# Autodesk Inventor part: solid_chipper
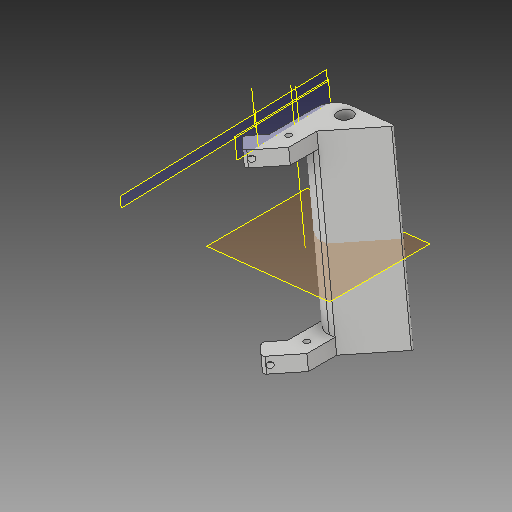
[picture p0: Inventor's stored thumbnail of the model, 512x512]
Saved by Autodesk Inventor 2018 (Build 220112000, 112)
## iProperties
Created: 2019-04
Part Number: solid_chipper
Material: Generic
Document SubType Name: Modeling
Designer: steve
Density: 1 g/cm^3
Appearance: Default
Created: 2019-05
Part Number: solid_chipper_3DPrint
Author: steve
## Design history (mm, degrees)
derived "side_assembly.iam"
sketch "Sketch1"
  geometry: L1 (-8.408, -4.5)-(67.651, -4.5); L2 (0, 0)-(22, 0) reference; L3 (11, 22.467)-(11, -9.554); L4 (17.451, -4.5)-(60.251, 38.3); L5 (17.451, 16.9)-(75.835, 16.9); L6 (26.011, -7.645)-(26.011, 49.186); L7 (36.557, -11.07)-(-5.296, 30.783); L8 (15, -3)-(7, -3); L9 (7, -3)-(7, 20); L10 (7, 20)-(15, 20); L11 (15, 20)-(15, -3); L12 (15, -3)-(7, 20); L13 (7, -3)-(15, 20); L14 (-15.558, -3)-(66.371, -3); L15 (28.487, -3)-(15, 10.487); L16 (15, 10.487)-(15, 20); L17 (-0.485, 35.485)-(40.435, -5.435); L18 (7.222, 27.778)-(2.465, 23.022); L19 (15, 20)-(7.222, 27.778); L20 (7.222, 27.778)-(2.465, 23.022); L21 (2.465, 23.022)-(7, 18.487); L22 (7, 18.487)-(7, -3); L23 (7, -3)-(28.487, -3); C1 r 7.5 at (16.699, 35.461); C2 r 4 at (16.699, 35.461) reference; C3 r 2.5 at (11, 16) reference; C4 r 1 at (11, 16); A1 r 21.4 centre (38.851, 16.9) between (17.451, 16.9) and (23.719, 1.768); 3 further points
  constraints: 44 end point, 16 point on line, 4 horizontal, 4 midpoint, 4 parallel, 3 centre point, 3 collinear, 3 perpendicular, 3 tangent, 3 vertical, 2 point on circle, 1 coincident, 1 concentric
  dimensions: "d17" = 4.5 distance between parallel lines of L1 L2; "d19" = 42.8 diameter of A1; "d21" = 15 diameter of C1; "d22" = 45 deg angle of L4 L1; "d23" = 8.56 distance from line of L6 L5.start; "d24" = 8 distance between parallel lines of L11 L9; "d25" = 3 distance between parallel lines of L2 L14; "d26" = 4 distance from line of C3.centre L10; "d32" = 11 distance from line of L18 C3.centre; "d39" = 2 diameter of C4
extrude "Extrusion1" new body sketch "Sketch1" distance "d40" = 5; taper "d41" = 0 deg
sketch "Sketch2"
  geometry: L1 (28.487, -3)-(15, 10.487) reference; L2 (7, -3)-(28.487, -3) reference; L3 (15, 10.487)-(7, 10.487); L4 (7, 10.487)-(7, -3); 1 further point
  constraints: 4 end point, 1 horizontal, 1 perpendicular
extrude "Extrusion2" join sketch "Sketch2" distance "d42" = 26.25; taper "d43" = 0 deg
mirror "Mirror1"
fillet "Fillet1" dims "d44" = 6
fillet "Fillet2" dims "d45" = 0.5
sketch "Sketch3"
  geometry: L1 (0, 0)-(0, -5) reference; L2 (0, -2.5)-(13.202, -2.5); L3 (2, -5)-(2, 20.813); 2 further points
  constraints: 4 end point, 2 point on line, 1 horizontal, 1 midpoint, 1 vertical
  dimensions: "d46" = 2 distance between parallel lines of L1 L3
hole "Hole1" sketch "Sketch3" at (2, -2.5) diameter "d47" = 2; stored, may be unused: countersink angle "d51" = 90 deg, drill point angle "d53" = 118 deg; dims "d48" = 6, "d49" = 4, "d50" = 2, "d52" = 8
sketch "Sketch4"
  geometry: L1 (6.727, 0)-(6.727, -5) reference; L2 (6.727, -2.5)-(0, -2.5); L3 (0, 0)-(0, -5) reference; L4 (0, -5)-(6.727, -5) reference; L5 (3.727, -5)-(3.727, 0); 2 further points
  constraints: 4 end point, 3 midpoint, 1 point on line, 1 vertical
  dimensions: "d54" = 3 distance between parallel lines of L1 L5
hole "Hole2" sketch "Sketch4" at (3.727, -2.5) diameter "d55" = 2; stored, may be unused: countersink angle "d59" = 90 deg, drill point angle "d61" = 118 deg; dims "d56" = 6, "d57" = 4, "d58" = 2, "d60" = 3
workplane "Work Plane3"
mirror "Mirror2"
fillet "Fillet3" dims "d62" = 1
sketch "Sketch5"
  geometry: L1 (-11.059, -1)-(37.671, -1); L2 (15, 10.362)-(15, -38.863); L3 (27.28, 3)-(13, 3) reference; L4 (7, -3)-(7, -18.487) reference; C1 r 2.5 at (15, -1); 1 further point
  constraints: 4 end point, 2 point on line, 1 centre point, 1 horizontal, 1 vertical
  dimensions: "d63" = 4 distance between parallel lines of L3 L1; "d64" = 8 distance between parallel lines of L4 L2; "d65" = 5 diameter of C1
extrude "Extrusion3" cut sketch "Sketch5" extent not by distance; stored distance "d66" = 10; taper "d67" = 0 deg
body "Solid1"
node "side_plate.ipt:1" dims "d0" = 10
body "Srf1"
workplane "Work Plane1"
workaxis "Work Axis1"
workaxis "Work Axis2"
node "base.ipt:1" dims "d0" = 10
workplane "Work Plane2"
workaxis "Work Axis1_1"
workaxis "Work Axis3"
node "side_assembly.iam_Bodies" dims "d0" = 10
other parameters: "d1" = 10.1, "d2" = 25, "d3" = 13, "d4" = 15, "d5" = 8, "d6" = 42.8, "d7" = 45 deg, "d8" = 38.1, "d9" = 6, "d10" = 2, "d11" = 3, "d12" = 3, "d13" = 3, "d14" = 0, "d15" = 17, "d20" = 2, "d27" = 22, "d28" = 12.1, "d29" = 14.6, "d30" = 3, "d31" = 2, "d33" = 0, "d34" = 26, "d35" = 14, "d36" = 6, "d37" = 27, "d38" = 3, "tol" = 0.1, "pitch" = 0.5, "roller_diam" = 15, "roller_bearing_dia" = 8, "ball_roller_angle" = 45 deg, "absorber_dia" = 12.1, "absorber_length" = 2.5, "d18" = 360 deg
